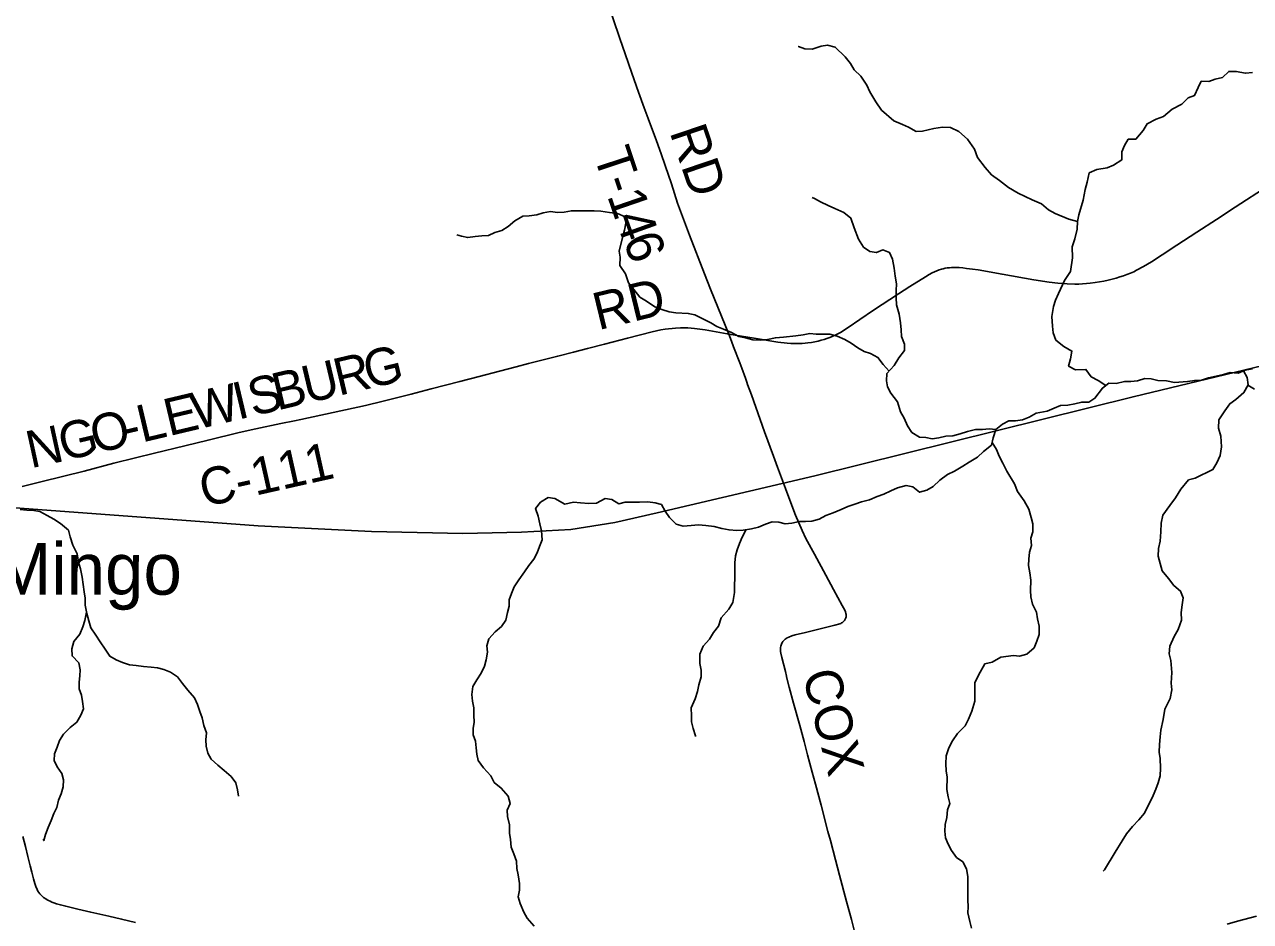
# Model space of a CAD drawing. Extents: x 0 to 1101, y 0 to 440.
# Drawn here: x 847.183 to 849.057, y 373.824 to 375.195 of the extents above; entities that cross this region are included whole.
import ezdxf

# ---------------------------------------------------------------- set-up
doc = ezdxf.new("R2010")
doc.units = 0
for name, color, linetype in [('GM_X_County_Road', 7, 'Continuous'), ('GM_X_County_Road_Text', 7, 'Continuous'), ('GM_X_Minor_River', 7, 'Continuous'), ('GM_X_Rail_Line', 7, 'Continuous'), ('GM_X_State_Route', 7, 'Continuous'), ('GM_X_Township_Road', 7, 'Continuous'), ('GM_X_Township_Road_Text', 7, 'Continuous'), ('GM_X_Unincorporated_Text', 7, 'Continuous')]:
    doc.layers.add(name, color=color, linetype=linetype)

msp = doc.modelspace()

# ---------------------------------------------------------------- linework, layer by layer
at = {"layer": 'GM_X_County_Road'}
for points in [[(848.2594, 374.722), (848.2978, 374.7156), (848.3341, 374.7099), (848.3483, 374.7082), (848.3542, 374.7078), (848.3601, 374.7076), (848.3657, 374.7076), (848.3714, 374.7078), (848.3759, 374.7081), (848.3801, 374.7086), (848.3855, 374.7093), (848.3906, 374.7102), (848.3958, 374.7113), (848.4004, 374.7125), (848.4052, 374.7139), (848.4093, 374.7152), (848.4136, 374.7168), (848.4175, 374.7184), (848.4237, 374.7213), (848.4298, 374.7247), (848.4419, 374.7323), (848.4594, 374.7441), (848.4805, 374.7585), (848.5188, 374.7838), (848.5361, 374.7948), (848.5598, 374.8097), (848.5654, 374.8129), (848.57, 374.8155), (848.5736, 374.8172), (848.5772, 374.8188), (848.5807, 374.8201), (848.5842, 374.8212), (848.5869, 374.8219), (848.5901, 374.8226), (848.5931, 374.8232), (848.5968, 374.8235), (848.5998, 374.8237), (848.6029, 374.8239), (848.6071, 374.8238), (848.6116, 374.8236), (848.6171, 374.8232), (848.6226, 374.8225), (848.6318, 374.8213), (848.6404, 374.82), (848.6771, 374.8135), (848.7255, 374.8052), (848.7488, 374.8015), (848.7624, 374.7999), (848.7767, 374.7988), (848.788, 374.7984), (848.7941, 374.7985), (848.7998, 374.7987), (848.8061, 374.7992), (848.8116, 374.7997), (848.8191, 374.8007), (848.8258, 374.8018), (848.8326, 374.803), (848.8392, 374.8045), (848.8452, 374.8059), (848.8513, 374.8075), (848.8571, 374.8093), (848.8626, 374.8111), (848.8678, 374.8129), (848.8731, 374.8151), (848.8782, 374.8174), (848.8827, 374.8196), (848.8931, 374.8252), (848.9054, 374.8327), (848.9216, 374.8431), (848.9444, 374.858), (848.9746, 374.8778), (849.0048, 374.8974), (849.0335, 374.9159), (849.084, 374.9488)], [(847.179, 374.4892), (847.1853, 374.4907), (847.2095, 374.4967), (847.274, 374.5127), (847.3191, 374.5245), (847.3522, 374.5328), (847.3812, 374.5398), (847.4277, 374.551), (847.4632, 374.56), (847.5109, 374.5716), (847.5364, 374.5773), (847.5747, 374.5854), (847.5954, 374.5897), (847.6051, 374.5917), (847.6543, 374.602), (847.7041, 374.613), (847.7307, 374.6194), (847.7735, 374.6301), (847.8042, 374.6382), (847.848, 374.6497), (847.8775, 374.6574), (847.9088, 374.6654), (847.9341, 374.6718), (847.9533, 374.6769), (847.9978, 374.6885), (848.0219, 374.6946), (848.0435, 374.7002), (848.0694, 374.7068), (848.1043, 374.7159), (848.1422, 374.7253), (848.1555, 374.7283), (848.162, 374.7295), (848.1671, 374.7302), (848.1725, 374.7308), (848.1776, 374.7313), (848.1854, 374.7317), (848.1902, 374.7317), (848.1967, 374.7315), (848.2066, 374.7307), (848.2231, 374.7284), (848.2568, 374.7225), (848.2594, 374.722)]]:
    msp.add_lwpolyline(points, dxfattribs=at)
at = {"layer": 'GM_X_Minor_River'}
for points in [[(848.7922, 374.8943), (848.7793, 374.8977), (848.758, 374.9064), (848.7478, 374.9121), (848.7375, 374.9213), (848.7231, 374.927), (848.7018, 374.9376), (848.687, 374.946), (848.673, 374.957), (848.6608, 374.9657), (848.651, 374.9768), (848.6392, 374.992), (848.635, 375.0045), (848.624, 375.0201), (848.6107, 375.0319), (848.5982, 375.038), (848.586, 375.0384), (848.5728, 375.0364), (848.5553, 375.0323), (848.5458, 375.0319), (848.5341, 375.0383), (848.5246, 375.0425), (848.5113, 375.0482), (848.4927, 375.0642), (848.484, 375.0771), (848.4748, 375.0923), (848.4703, 375.1026), (848.4612, 375.1163), (848.4509, 375.1258), (848.4452, 375.1357), (848.4372, 375.146), (848.4217, 375.1608), (848.4103, 375.1635), (848.4004, 375.1619), (848.3868, 375.1574), (848.3754, 375.1581), (848.3659, 375.1615), (848.3663, 375.1619)], [(848.8356, 374.6435), (848.8239, 374.6509), (848.8133, 374.6566), (848.8053, 374.668), (848.7894, 374.6676), (848.7788, 374.6729), (848.7814, 374.6843), (848.7837, 374.6961), (848.7715, 374.7029), (848.759, 374.7128), (848.7552, 374.7242), (848.754, 374.7341), (848.7533, 374.7489), (848.7555, 374.7642), (848.7589, 374.7737), (848.7635, 374.7843), (848.7725, 374.8041), (848.7816, 374.8178), (848.7846, 374.8387), (848.7842, 374.8555), (848.788, 374.8676), (848.7918, 374.8825), (848.7922, 374.8939), (848.7944, 374.9042), (848.8012, 374.9266), (848.8039, 374.943), (848.8069, 374.9544), (848.8103, 374.9685), (848.822, 374.9734), (848.8376, 374.9761), (848.8471, 374.9803), (848.8599, 374.9883), (848.8603, 375.0008), (848.8641, 375.0103), (848.8698, 375.0199), (848.8815, 375.0202), (848.8929, 375.0332), (848.8986, 375.0435), (848.9126, 375.0503), (848.924, 375.0545), (848.9368, 375.0659), (848.9516, 375.0735), (848.9615, 375.0831), (848.9713, 375.0869), (848.9766, 375.099), (848.9816, 375.1086), (848.9933, 375.1082), (849.0028, 375.1116), (849.0142, 375.1143), (849.0236, 375.1234), (849.035, 375.1234), (849.0491, 375.1208), (849.0597, 375.1219)], [(848.6677, 374.5762), (848.6571, 374.577), (848.6469, 374.5762), (848.6366, 374.5762), (848.6241, 374.5732), (848.6127, 374.5694), (848.6018, 374.5663), (848.5911, 374.5659), (848.5805, 374.5636), (848.5703, 374.5621), (848.5604, 374.564), (848.5509, 374.5644), (848.5392, 374.5716), (848.5323, 374.5819), (848.5274, 374.5933), (848.5217, 374.6032), (848.5171, 374.6187), (848.5072, 374.6317), (848.5019, 374.6412), (848.5004, 374.6507), (848.5008, 374.6617), (848.5121, 374.6739), (848.5193, 374.6857), (848.5276, 374.6971), (848.5276, 374.7066), (848.5231, 374.7184), (848.5227, 374.7283), (848.5219, 374.7393), (848.5196, 374.7526), (848.5154, 374.7667), (848.515, 374.7773), (848.515, 374.7888), (848.5158, 374.7986), (848.5135, 374.8104), (848.5123, 374.8226), (848.5097, 374.8363), (848.5051, 374.8466), (848.4945, 374.8507), (848.485, 374.8466), (848.4748, 374.8485), (848.4653, 374.8549), (848.4573, 374.8671), (848.4508, 374.8846), (848.4459, 374.8994), (848.4352, 374.9078), (848.4216, 374.9139), (848.411, 374.9184), (848.3996, 374.9241), (848.3901, 374.9295), (848.3867, 374.931)], [(848.5042, 374.6654), (848.4954, 374.6758), (848.4871, 374.6864), (848.4761, 374.6925), (848.4662, 374.6955), (848.4563, 374.7012), (848.4461, 374.7081), (848.4366, 374.7138), (848.4248, 374.7191), (848.4138, 374.7221), (848.404, 374.7218), (848.393, 374.7217), (848.3831, 374.7229), (848.3729, 374.721), (848.3615, 374.7195), (848.3429, 374.7172), (848.3304, 374.7164), (848.3183, 374.7137), (848.308, 374.7126), (848.2959, 374.7133), (848.2849, 374.7164), (848.2746, 374.7183), (848.2636, 374.7247), (848.2511, 374.7293), (848.2412, 374.7338), (848.2318, 374.7392), (848.2075, 374.7513), (848.1972, 374.7536), (848.1783, 374.7547), (848.168, 374.7563), (848.157, 374.7597), (848.146, 374.7635), (848.1335, 374.7726), (848.1232, 374.7787), (848.1141, 374.7901), (848.1061, 374.8004), (848.1012, 374.814), (848.0925, 374.827), (848.0932, 374.8395), (848.0917, 374.849), (848.097, 374.8696), (848.1, 374.881), (848.1019, 374.8917), (848.1007, 374.9012), (848.0889, 374.9065), (848.0768, 374.908), (848.0639, 374.9099), (848.0533, 374.9103), (848.0423, 374.9103), (848.032, 374.9106), (848.0188, 374.9106), (848.0078, 374.9084), (847.9975, 374.908), (847.9869, 374.9095), (847.9755, 374.9072), (847.9657, 374.9045), (847.9543, 374.903), (847.9444, 374.9022), (847.9323, 374.895), (847.9221, 374.8866), (847.9122, 374.8802), (847.9016, 374.8771), (847.8921, 374.8729), (847.8815, 374.8722), (847.8713, 374.871), (847.8603, 374.8695), (847.8508, 374.8718), (847.8436, 374.8737)], [(849.0598, 374.6689), (849.0488, 374.667), (849.0378, 374.6624), (849.0257, 374.6635), (849.0154, 374.6605), (849.0044, 374.6578), (848.9927, 374.6551), (848.9821, 374.6517), (848.9715, 374.6513), (848.9605, 374.6494), (848.9407, 374.6479), (848.9286, 374.6505), (848.9153, 374.6513), (848.9047, 374.6536), (848.8952, 374.6543), (848.8838, 374.6505), (848.8736, 374.6494), (848.8641, 374.6494), (848.8516, 374.6467), (848.8402, 374.6471), (848.8304, 374.6395), (848.819, 374.6239), (848.8095, 374.6181), (848.7989, 374.6181), (848.7883, 374.6155), (848.7777, 374.6136), (848.7663, 374.6128), (848.7565, 374.609), (848.7458, 374.6044), (848.7292, 374.6014), (848.7182, 374.5953), (848.7083, 374.5911), (848.6977, 374.5896), (848.6874, 374.5896), (848.6776, 374.5842), (848.6677, 374.5762), (848.6636, 374.5637), (848.6606, 374.5523), (848.6488, 374.5424), (848.6393, 374.534), (848.6265, 374.5264), (848.617, 374.5203), (848.6045, 374.5127), (848.5935, 374.5074)], [(849.0462, 374.6659), (849.0515, 374.6559), (849.0534, 374.6445), (849.0466, 374.6327), (849.0344, 374.6221), (849.025, 374.6156), (849.0174, 374.6046), (849.0083, 374.5909), (849.0076, 374.5783), (849.0114, 374.5658), (849.0122, 374.5498), (849.0103, 374.5365), (849.0053, 374.5255), (848.9993, 374.5152), (848.9724, 374.5019), (848.9621, 374.4992), (848.9504, 374.4848), (848.9421, 374.4715), (848.9334, 374.4601), (848.9228, 374.4452), (848.9201, 374.4331), (848.9197, 374.4197), (848.9186, 374.4057), (848.916, 374.3943), (848.9156, 374.3825), (848.9217, 374.3604), (848.9316, 374.3487), (848.9396, 374.3377), (848.9498, 374.3293), (848.9536, 374.319), (848.9521, 374.3084), (848.951, 374.2966), (848.9514, 374.2848), (848.9461, 374.2704), (848.94, 374.2597), (848.9332, 374.2449), (848.9325, 374.2335), (848.9351, 374.2233), (848.9363, 374.2047), (848.9355, 374.1887), (848.9363, 374.1781), (848.934, 374.1651), (848.9257, 374.1488), (848.9231, 374.1332), (848.9197, 374.1165), (848.9189, 374.1062), (848.9178, 374.0949), (848.9174, 374.0831), (848.9186, 374.0732), (848.9194, 374.0584), (848.9186, 374.0466), (848.9156, 374.036), (848.9122, 374.0265), (848.908, 374.0166), (848.8948, 373.99), (848.8861, 373.9794), (848.8766, 373.9695), (848.8671, 373.9581), (848.8607, 373.9475), (848.8497, 373.9304), (848.8338, 373.9034), (848.8315, 373.9011)], [(849.0529, 374.6438), (849.0629, 374.6381)], [(848.6617, 374.5565), (848.6685, 374.5458), (848.6727, 374.5352), (848.678, 374.5249), (848.6845, 374.5127), (848.6959, 374.4934), (848.7008, 374.4816), (848.7107, 374.4671), (848.7179, 374.4546), (848.7217, 374.4417), (848.724, 374.4322), (848.724, 374.4196), (848.721, 374.4101), (848.7222, 374.3991), (848.7188, 374.3888), (848.718, 374.3782), (848.7176, 374.3683), (848.7196, 374.3573), (848.7211, 374.3459), (848.7207, 374.3299), (848.7211, 374.3204), (848.7234, 374.309), (848.7295, 374.2972), (848.731, 374.287), (848.7337, 374.2756), (848.7337, 374.263), (848.7303, 374.2528), (848.7261, 374.2425), (848.7151, 374.2326), (848.7038, 374.2299), (848.6943, 374.2307), (848.6749, 374.228), (848.6621, 374.2208), (848.6507, 374.2181), (848.6412, 374.2006), (848.6355, 374.1892), (848.6356, 374.1611), (848.6306, 374.1459), (848.6257, 374.1334), (848.6204, 374.1231), (848.6091, 374.1117), (848.6011, 374.1003), (848.5958, 374.0897), (848.5917, 374.0775), (848.5909, 374.065), (848.5917, 374.0547), (848.5932, 374.0449), (848.5928, 374.0259), (848.5947, 374.0145), (848.597, 374.0046), (848.5936, 373.9947), (848.5925, 373.9833), (848.5899, 373.9727), (848.5895, 373.9621), (848.5906, 373.9522), (848.5944, 373.9423), (848.5998, 373.9329), (848.6074, 373.9222), (848.6168, 373.9154), (848.6225, 373.9048), (848.6245, 373.893), (848.6248, 373.8805), (848.6249, 373.8573), (848.6253, 373.8467), (848.6249, 373.8372), (848.6275, 373.8243), (848.6302, 373.8141)], [(848.5935, 374.5074), (848.5821, 374.499), (848.5715, 374.4891), (848.562, 374.4834), (848.551, 374.4803), (848.5408, 374.4887), (848.5302, 374.4906), (848.5173, 374.4868), (848.507, 374.4826), (848.4964, 374.4773), (848.4862, 374.4738), (848.4744, 374.4685), (848.4619, 374.4655), (848.4521, 374.462), (848.4414, 374.4586), (848.4312, 374.454), (848.4187, 374.4487), (848.4077, 374.4449), (848.3975, 374.4392), (848.3861, 374.4361), (848.3766, 374.4354), (848.3671, 374.4354), (848.3557, 374.4331), (848.3455, 374.4319), (848.336, 374.4346), (848.3254, 374.435), (848.3152, 374.4316), (848.3045, 374.427), (848.2939, 374.4243), (848.2814, 374.4224), (848.2716, 374.4216), (848.2598, 374.4228), (848.2488, 374.4247), (848.237, 374.4277), (848.2241, 374.4296), (848.2128, 374.4304), (848.2018, 374.4296), (848.1896, 374.4284), (848.1786, 374.4315), (848.1684, 374.4417), (848.1619, 374.4512), (848.1562, 374.4615), (848.1467, 374.4642), (848.1357, 374.4657), (848.1228, 374.4653), (848.1103, 374.4649), (848.1008, 374.4649), (848.091, 374.4626), (848.0803, 374.4691), (848.0701, 374.4706), (848.0572, 374.4634), (848.0455, 374.463), (848.0326, 374.4641), (848.0219, 374.4652), (848.0087, 374.4622), (847.9931, 374.4709), (847.9829, 374.4721), (847.9715, 374.4652), (847.9639, 374.4553), (847.9681, 374.4436), (847.9704, 374.4321), (847.9727, 374.4215), (847.9742, 374.4078), (847.97, 374.3972), (847.9663, 374.3877), (847.9613, 374.3782), (847.9538, 374.3683), (847.947, 374.3584), (847.9382, 374.3462), (847.9314, 374.3359), (847.9273, 374.3257), (847.9235, 374.3158), (847.9235, 374.3063), (847.9212, 374.2964), (847.9186, 374.2846), (847.9118, 374.2751), (847.9023, 374.2668), (847.8924, 374.2561), (847.8894, 374.2455), (847.8906, 374.236), (847.8883, 374.2242), (847.8857, 374.2143), (847.8807, 374.204), (847.8743, 374.1934), (847.8679, 374.1835), (847.8664, 374.171), (847.8675, 374.1611), (847.8694, 374.1508), (847.8694, 374.1394), (847.8702, 374.1288), (847.8683, 374.1193), (847.8683, 374.1094), (847.8721, 374.0999), (847.8733, 374.0897), (847.874, 374.0798), (847.8763, 374.0703), (847.8843, 374.0589), (847.8957, 374.0468), (847.9006, 374.0369), (847.9113, 374.0282), (847.9219, 374.016)], [(847.1759, 374.454), (847.1862, 374.4528), (847.1968, 374.4523), (847.2063, 374.4507), (847.2173, 374.4449), (847.2276, 374.439), (847.2378, 374.4325), (847.2499, 374.4221), (847.2524, 374.4122), (847.2565, 374.3995), (847.2629, 374.3862), (847.2654, 374.3736), (847.2684, 374.3633), (847.2709, 374.3507), (847.2723, 374.3392), (847.2738, 374.3282), (847.2756, 374.3186), (847.2755, 374.3076), (847.2777, 374.295), (847.281, 374.2836), (847.2839, 374.2732), (847.2918, 374.2621), (847.2982, 374.2518), (847.3057, 374.2407), (847.3129, 374.2296), (847.3227, 374.2241), (847.3322, 374.2203), (847.3432, 374.2167), (847.3531, 374.2155), (847.3645, 374.2139), (847.3763, 374.213), (847.3858, 374.2121), (847.3957, 374.2094), (847.4059, 374.2051), (847.4165, 374.1981), (847.4244, 374.1878), (847.4323, 374.1778), (847.4425, 374.1663), (847.447, 374.156), (847.4507, 374.1453), (847.454, 374.1354), (847.457, 374.1239), (847.4607, 374.1125), (847.4598, 374.1018), (847.4601, 374.0923), (847.4627, 374.0816), (847.4679, 374.0721), (847.4781, 374.0632), (847.4879, 374.0551), (847.4985, 374.0459), (847.5057, 374.036), (847.5082, 374.0253), (847.51, 374.0157)], [(848.286, 374.4231), (848.2799, 374.4118), (848.2757, 374.4019), (848.272, 374.3924), (848.2697, 374.3829), (848.2686, 374.3726), (848.2686, 374.3487), (848.2679, 374.3388), (848.2682, 374.327), (848.2656, 374.3118), (848.2592, 374.3015), (848.2478, 374.2882), (848.2436, 374.2757), (848.2357, 374.2658), (848.23, 374.2559), (848.2202, 374.2449), (848.2152, 374.2327), (848.2149, 374.2183), (848.2168, 374.2084), (848.2172, 374.1981), (848.2134, 374.186), (848.2115, 374.1757), (848.2081, 374.1643), (848.2017, 374.1506), (848.2021, 374.1388), (848.2021, 374.1293), (848.2047, 374.1191), (848.2082, 374.1081), (848.2082, 374.1069)], [(847.2774, 374.2968), (847.2749, 374.2844), (847.2718, 374.2745), (847.2671, 374.2635), (847.2579, 374.2522), (847.2551, 374.2412), (847.2554, 374.2301), (847.2656, 374.2197), (847.2677, 374.2091), (847.2673, 374.1995), (847.2664, 374.19), (847.266, 374.1798), (847.2697, 374.1702), (847.2715, 374.1603), (847.2729, 374.1492), (847.269, 374.1398), (847.2624, 374.1288), (847.2525, 374.1205), (847.2421, 374.1107), (847.2363, 374.1009), (847.2328, 374.0906), (847.2285, 374.0804), (847.228, 374.0701), (847.2325, 374.0606), (847.2397, 374.0506), (847.2422, 374.0407), (847.2418, 374.0301), (847.2386, 374.0191), (847.2347, 374.0096), (847.2319, 373.9986), (847.2277, 373.9891), (847.2234, 373.9785), (847.2187, 373.9679), (847.2148, 373.9573), (847.2121, 373.9478), (847.2109, 373.9493)], [(847.9219, 374.016), (847.9249, 374.0046), (847.9204, 373.9944), (847.9212, 373.9845), (847.9238, 373.972), (847.9239, 373.9591), (847.9254, 373.9496), (847.9265, 373.9378), (847.9307, 373.9276), (847.9345, 373.9162), (847.9353, 373.9052), (847.9372, 373.8953), (847.9395, 373.8824), (847.9391, 373.8721), (847.9372, 373.8619), (847.9403, 373.8516), (847.946, 373.8387), (847.9509, 373.8293), (847.9615, 373.8171)]]:
    msp.add_lwpolyline(points, dxfattribs=at)
at = {"layer": 'GM_X_Rail_Line'}
msp.add_lwpolyline([(847.0512, 374.4653), (847.5396, 374.4291), (847.7129, 374.4202), (847.8527, 374.4173), (847.9426, 374.4192), (848.0178, 374.4236), (848.0853, 374.4341), (848.1498, 374.449), (848.3906, 374.5054), (848.8773, 374.6263), (849.2451, 374.7149), (849.9422, 374.8869), (850.1863, 374.9448), (850.3164, 374.976), (850.3801, 374.9962), (850.4508, 375.0223), (850.9258, 375.2486)], dxfattribs=at)
at = {"layer": 'GM_X_State_Route'}
for points in [[(847.1801, 373.9539), (847.184, 373.9388), (847.1878, 373.9238), (847.1915, 373.9093), (847.194, 373.8997), (847.1966, 373.8895), (847.1984, 373.8823), (847.1999, 373.8776), (847.2018, 373.8731), (847.2032, 373.8705), (847.2046, 373.8684), (847.2063, 373.8664), (847.2081, 373.8643), (847.2098, 373.8627), (847.2117, 373.8611), (847.2152, 373.8587), (847.2173, 373.8574), (847.2194, 373.8562), (847.2218, 373.8551), (847.2244, 373.8539), (847.2275, 373.8527), (847.2313, 373.8513), (847.2376, 373.8496), (847.2457, 373.8475), (847.2644, 373.8429), (847.2838, 373.8384), (847.3116, 373.8323), (847.331, 373.8279), (847.3522, 373.8229)], [(849.0209, 373.8203), (849.0371, 373.8246), (849.0564, 373.8296), (849.066, 373.8322)]]:
    msp.add_lwpolyline(points, dxfattribs=at)
at = {"layer": 'GM_X_Township_Road'}
for points in [[(848.101, 375.1503), (848.0928, 375.174), (848.0825, 375.2039), (848.0722, 375.2341), (848.0608, 375.2662), (848.0584, 375.273)], [(848.2594, 374.722), (848.2481, 374.7496), (848.2313, 374.7906), (848.2219, 374.8143), (848.1994, 374.8733), (848.1809, 374.9221), (848.1716, 374.9515), (848.1618, 374.9798), (848.1561, 374.9973), (848.1489, 375.0176), (848.136, 375.0514), (848.1299, 375.0681), (848.1212, 375.0919), (848.1112, 375.1209), (848.101, 375.1503)], [(848.266, 374.7042), (848.2619, 374.7152), (848.2594, 374.722)], [(848.2868, 374.6484), (848.2846, 374.6547), (848.2791, 374.6699), (848.2761, 374.678), (848.2667, 374.7024), (848.266, 374.7042)], [(848.452, 373.8069), (848.4466, 373.8273), (848.4393, 373.8549), (848.4287, 373.8952), (848.4223, 373.9185), (848.4145, 373.948), (848.4109, 373.9618), (848.4004, 374.002), (848.3916, 374.0343), (848.3867, 374.0522), (848.3797, 374.0791), (848.3744, 374.0994), (848.3678, 374.1239), (848.3584, 374.158), (848.3517, 374.1826), (848.3477, 374.1982), (848.3476, 374.1994), (848.3459, 374.2061), (848.3402, 374.2277), (848.3387, 374.2343), (848.3383, 374.2371), (848.3382, 374.2393), (848.3382, 374.2413), (848.3383, 374.243), (848.3387, 374.245), (848.3392, 374.2466), (848.3397, 374.2479), (848.3404, 374.2495), (848.3413, 374.2509), (848.3421, 374.2521), (848.343, 374.2533), (848.3441, 374.2544), (848.3455, 374.2555), (848.347, 374.2567), (848.3487, 374.2578), (848.3508, 374.2589), (848.3554, 374.2607), (848.3608, 374.2623), (848.3765, 374.2659), (848.3989, 374.2713), (848.4212, 374.277), (848.4289, 374.2792), (848.4304, 374.2799), (848.4317, 374.2806), (848.433, 374.2814), (848.4343, 374.2823), (848.4353, 374.2833), (848.436, 374.2841), (848.4368, 374.2853), (848.4373, 374.2862), (848.4378, 374.2873), (848.4382, 374.2885), (848.4385, 374.29), (848.4387, 374.2916), (848.4386, 374.2934), (848.4382, 374.2952), (848.4376, 374.2973), (848.4365, 374.2999), (848.4328, 374.307), (848.4193, 374.3319), (848.4077, 374.3534), (848.3901, 374.3856), (848.3772, 374.4097), (848.3712, 374.422), (848.3661, 374.4333), (848.3613, 374.4454), (848.3527, 374.4681), (848.3461, 374.4861), (848.3339, 374.5186), (848.3275, 374.5355), (848.3137, 374.5728), (848.2938, 374.629), (848.2881, 374.6448), (848.2868, 374.6484)]]:
    msp.add_lwpolyline(points, dxfattribs=at)

# ---------------------------------------------------------------- texts
at = {"layer": 'GM_X_County_Road_Text'}
for s, height, rotation, p in [('RD', 0.05682, 13.6817, (848.0597, 374.7278)), ('G', 0.0568, 13.3506, (847.7083, 374.6382)), ('R', 0.0568, 13.3513, (847.6629, 374.6275)), ('B', 0.0568, 13.3499, (847.5688, 374.6051)), ('U', 0.0568, 13.3471, (847.6143, 374.6159)), ('W', 0.0568, 13.3503, (847.4448, 374.5757)), ('I', 0.0568, 13.3509, (847.5088, 374.5909)), ('S', 0.0568, 13.3483, (847.5315, 374.5963)), ('E', 0.0568, 13.346, (847.4034, 374.5659)), ('L', 0.0568, 13.3502, (847.3621, 374.5561)), ('G', 0.0568, 13.3566, (847.2421, 374.5276)), ('O', 0.0568, 13.3471, (847.2907, 374.5391)), ('N', 0.0568, 12.3194, (847.1921, 374.5167)), ('-', 0.0568, 13.3556, (847.3394, 374.5507)), ('C-111', 0.05682, 12.6152, (847.4571, 374.4574))]:
    msp.add_text(s, height=height, rotation=rotation, dxfattribs=at).set_placement(p)
at = {"layer": 'GM_X_Township_Road_Text'}
for s, height, rotation, p in [('RD', 0.05682, 288.7382, (848.1683, 375.031)), ('T', 0.0568, 288.3184, (848.0519, 374.9969)), ('-', 0.0568, 288.4846, (848.0653, 374.9564)), ('1', 0.0568, 288.9918, (848.0729, 374.9338)), ('4', 0.0568, 289.7719, (848.0846, 374.8999)), ('6', 0.0568, 290.98, (848.0969, 374.8657)), ('COX', 0.05682, 284.4292, (848.3714, 374.2026))]:
    msp.add_text(s, height=height, rotation=rotation, dxfattribs=at).set_placement(p)
at = {"layer": 'GM_X_Unincorporated_Text'}
msp.add_text('Mingo', height=0.07898, rotation=0, dxfattribs=at).set_placement((847.1356, 374.3237))

doc.saveas('drawing.dxf')
